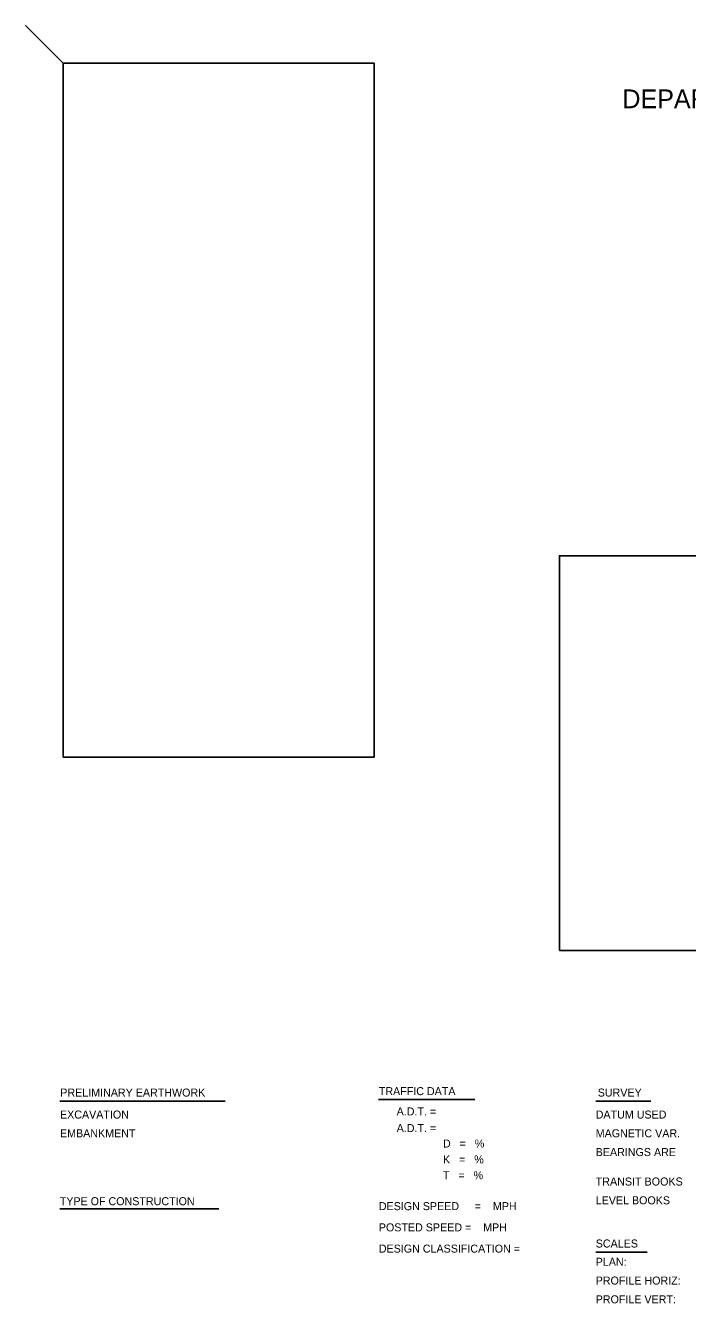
# Model space of a CAD drawing. Extents: x 0.19 to 2.82, y 0.04 to 1.79.
# Drawn here: x 0.192 to 1.075, y 0.088 to 1.792 of the extents above; entities that cross this region are included whole.
import ezdxf

# ---------------------------------------------------------------- set-up
doc = ezdxf.new("R2010")
doc.units = 0
for name, color, linetype in [('Annotation', 7, 'Continuous'), ('Layout Map Info', 7, 'Continuous'), ('Seal', 7, 'Continuous'), ('Standard Info', 7, 'Continuous')]:
    doc.layers.add(name, color=color, linetype=linetype)

msp = doc.modelspace()

# ---------------------------------------------------------------- linework, layer by layer
at = {"layer": 'Annotation'}
msp.add_lwpolyline([(0.2417, 0.8166), (0.6565, 0.8166), (0.6565, 1.7417), (0.2417, 1.7417)], close=True, dxfattribs=at)
at = {"layer": 'Layout Map Info'}
msp.add_lwpolyline([(0.9038, 0.5585), (2.1045, 0.5585), (2.1045, 1.0849), (0.9038, 1.0849)], close=True, dxfattribs=at)
at = {"layer": 'Seal'}
for p, q in [((0.2376, 0.3579), (0.4578, 0.3579)), ((0.6625, 0.3599), (0.7909, 0.3599)), ((0.9522, 0.3579), (1.0257, 0.3579)), ((0.9522, 0.1568), (1.0208, 0.1568))]:
    msp.add_line(p, q, dxfattribs=at)
at = {"layer": 'Standard Info'}
for p, q in [((0.1917, 1.7917), (0.2417, 1.7417)), ((0.2376, 0.2142), (0.4497, 0.2142))]:
    msp.add_line(p, q, dxfattribs=at)

# ---------------------------------------------------------------- texts
for s, height, p in [('DEPARTMENT  OF  TRANSPORTATION  AND  DEVELOPMENT', 0.025, (0.9878, 1.6815)), ('PRELIMINARY EARTHWORK', 0.01067, (0.238, 0.364)), ('TRAFFIC DATA', 0.01067, (0.6629, 0.3659)), ('SURVEY', 0.01067, (0.9549, 0.364)), ('EXCAVATION                  ', 0.01067, (0.2376, 0.3347)), ('      A.D.T. =        ', 0.01067, (0.6629, 0.3388)), ('DATUM USED                 ', 0.01067, (0.9522, 0.3347)), ('      A.D.T. =        ', 0.01067, (0.6629, 0.3167)), ('EMBANKMENT                 ', 0.01067, (0.2376, 0.3097)), ('D   =   % ', 0.01067, (0.7485, 0.2961)), ('MAGNETIC VAR.                 ', 0.01067, (0.9522, 0.3097)), ('BEARINGS ARE                 ', 0.01067, (0.9522, 0.2847)), ('K   =   % ', 0.01067, (0.7485, 0.2749)), ('T   =   % ', 0.01067, (0.7485, 0.2538)), ('TRANSIT BOOKS                 ', 0.0107, (0.9522, 0.2454)), ('TYPE OF CONSTRUCTION', 0.01067, (0.2373, 0.2192)), ('DESIGN SPEED', 0.01067, (0.6629, 0.2126)), ('=    MPH', 0.01067, (0.7909, 0.2126)), ('LEVEL BOOKS                 ', 0.01067, (0.9522, 0.2204)), ('POSTED SPEED =    MPH', 0.01067, (0.6629, 0.1843)), ('SCALES', 0.01067, (0.9522, 0.1628)), ('DESIGN CLASSIFICATION =     ', 0.01067, (0.6629, 0.156)), ('PLAN:                 ', 0.01067, (0.9522, 0.1384)), ('PROFILE HORIZ:                 ', 0.01067, (0.9522, 0.1134)), ('PROFILE VERT:                 ', 0.01067, (0.9522, 0.0884))]:
    msp.add_text(s, height=height, dxfattribs=at).set_placement(p)

doc.saveas('drawing.dxf')
